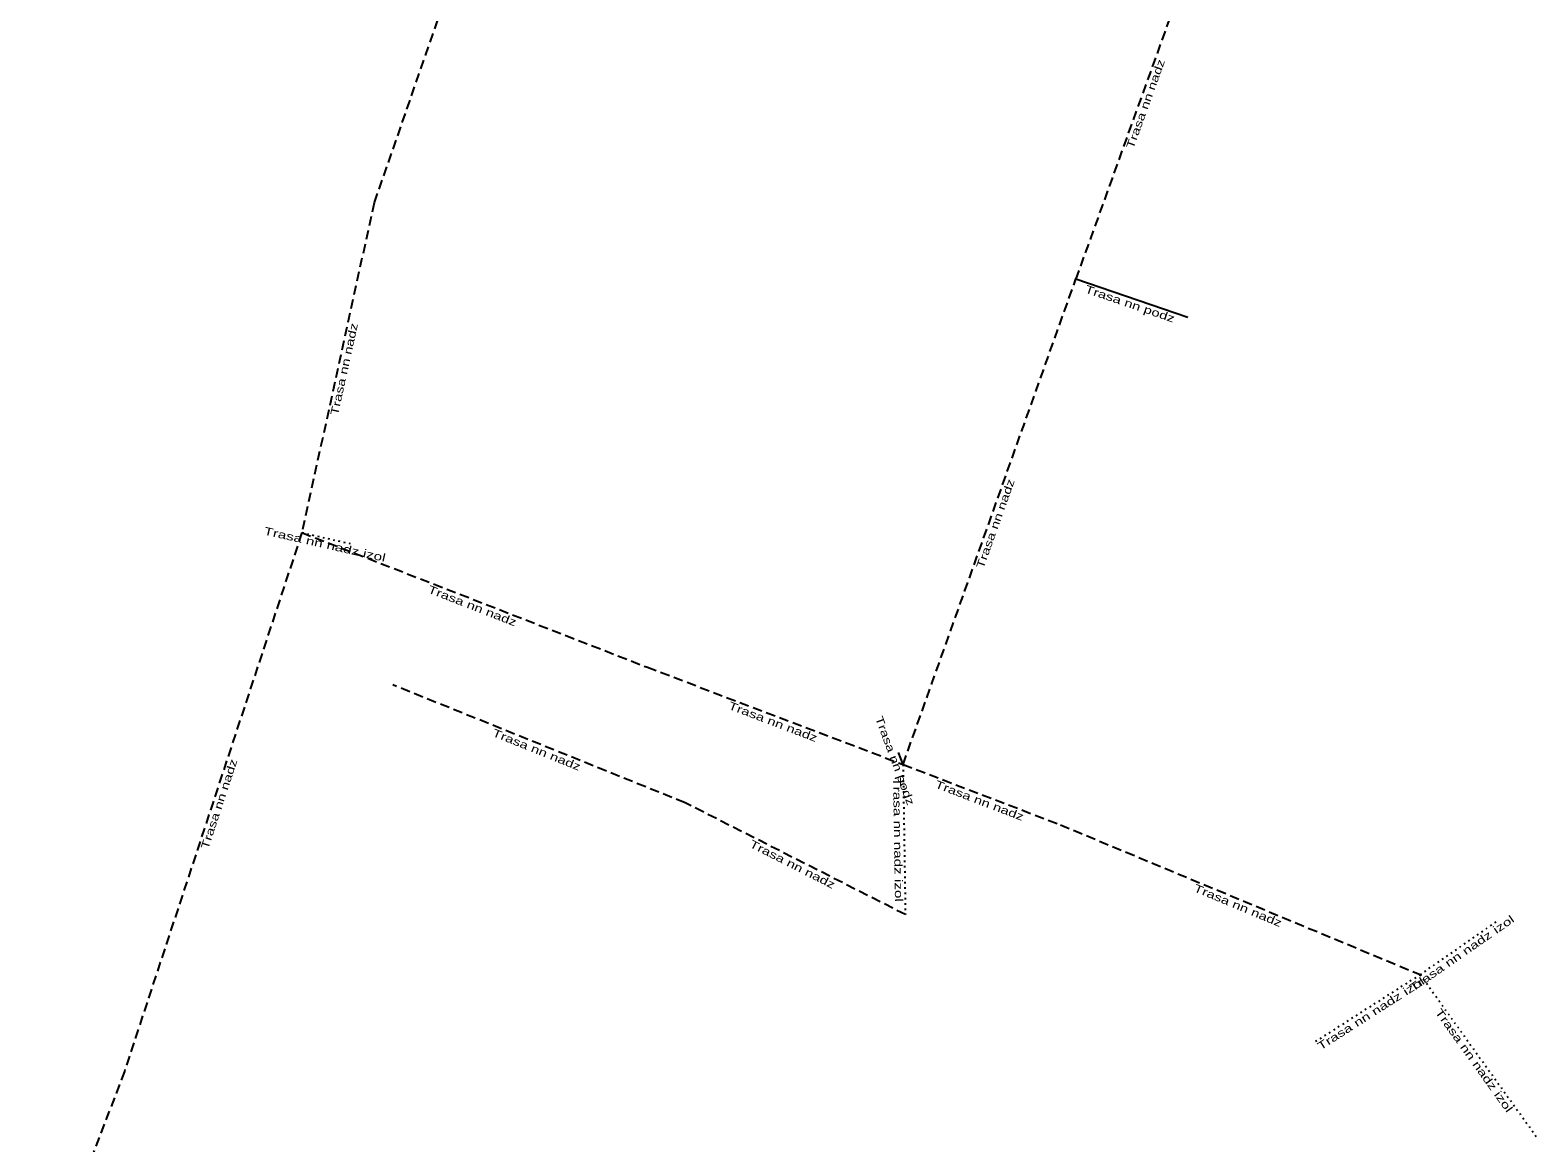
# Model space of a CAD drawing. Extents: x -733620 to -732615, y -1025255 to -1024617.
# Drawn here: x -733019.7 to -732923.7, y -1025041.4 to -1024970.5 of the extents above; entities that cross this region are included whole.
import ezdxf
from ezdxf.enums import TextEntityAlignment as Align

# ---------------------------------------------------------------- set-up
doc = ezdxf.new("R2010")
doc.units = 0
doc.header["$LTSCALE"] = 0.2
doc.linetypes.add('DOTTED', pattern=[1.5, 0.3, -1.2])
doc.linetypes.add('MEDIUM_DASHED', pattern=[4.5, 3, -1.5])
doc.layers.add('11', color=7, linetype='MEDIUM_DASHED', lineweight=25)
doc.layers.add('20', color=7, linetype='Continuous')

msp = doc.modelspace()

# ---------------------------------------------------------------- linework, layer by layer
at = {"layer": '11'}
for p, q in [((-732986.99, -1024950.3), (-732997.8, -1024981.5)), ((-732945, -1024963.8), (-732953.11, -1024986.33)), ((-732997.8, -1024981.5), (-733002.4, -1025002.5)), ((-732964.12, -1025017.26), (-732953.11, -1024986.33)), ((-733002.4, -1025002.5), (-733013.7, -1025036.8)), ((-733002.4, -1025002.5), (-732980.4, -1025011.07)), ((-732980.4, -1025011.07), (-732964.12, -1025017.26)), ((-732978, -1025019.7), (-732996.6, -1025012.2)), ((-732964.12, -1025017.26), (-732954.1, -1025021.1)), ((-732963.97, -1025026.82), (-732978, -1025019.7)), ((-732954.1, -1025021.1), (-732931.19, -1025030.64)), ((-733013.7, -1025036.8), (-733019.7, -1025052.6))]:
    msp.add_line(p, q, dxfattribs=at)
at = {"layer": '11', "linetype": 'Continuous'}
for p, q in [((-732953.11, -1024986.33), (-732945.98, -1024988.77)), ((-732964.12, -1025017.26), (-732964.4, -1025016.5))]:
    msp.add_line(p, q, dxfattribs=at)
at = {"layer": '11', "linetype": 'DOTTED'}
for p, q in [((-733002.4, -1025002.5), (-732999.3, -1025003.2)), ((-732964.12, -1025017.26), (-732963.97, -1025026.82)), ((-732931.19, -1025030.64), (-732926.35, -1025027.28)), ((-732931.19, -1025030.64), (-732937.91, -1025034.94)), ((-732931.19, -1025030.64), (-732923.7, -1025041.1))]:
    msp.add_line(p, q, dxfattribs=at)

# ---------------------------------------------------------------- texts
at = {"layer": '20'}
for s, rotation, width, p in [('Trasa nn nadz', 70.203, 1.4, (-732948.4433, -1024975.2842)), ('Trasa nn podz', 341.108, 1.4, (-732949.7554, -1024988.1639)), ('Trasa nn nadz', 77.645, 1.4, (-732999.4643, -1024992.139)), ('Trasa nn nadz', 70.406, 1.4, (-732958.0018, -1025002.0123)), ('Trasa nn nadz izol', 347.276, 1.45, (-733000.9926, -1025003.4836)), ('Trasa nn nadz', 338.717, 1.4, (-732991.6352, -1025007.3899)), ('Trasa nn nadz', 339.182, 1.4, (-732972.4903, -1025014.7723)), ('Trasa nn nadz', 338.039, 1.4, (-732987.543, -1025016.5524)), ('Trasa nn podz', 290.225, 1.4, (-732964.8691, -1025017.1041)), ('Trasa nn nadz', 71.766, 1.4, (-733007.4325, -1025019.8527)), ('Trasa nn nadz izol', 270.899, 1.45, (-732964.6942, -1025022.0486)), ('Trasa nn nadz', 339.031, 1.4, (-732959.342, -1025019.7868)), ('Trasa nn nadz', 333.093, 1.4, (-732971.2786, -1025023.8397)), ('Trasa nn nadz', 337.393, 1.4, (-732942.8946, -1025026.4696)), ('Trasa nn nadz izol', 34.769, 1.45, (-732928.3991, -1025029.4942)), ('Trasa nn nadz izol', 32.614, 1.45, (-732934.1982, -1025033.3371)), ('Trasa nn nadz izol', 305.605, 1.45, (-732927.973, -1025036.248))]:
    msp.add_text(s, height=0.5, rotation=rotation, dxfattribs=dict(at, width=width)).set_placement(p, align=Align.CENTER)

doc.saveas('drawing.dxf')
